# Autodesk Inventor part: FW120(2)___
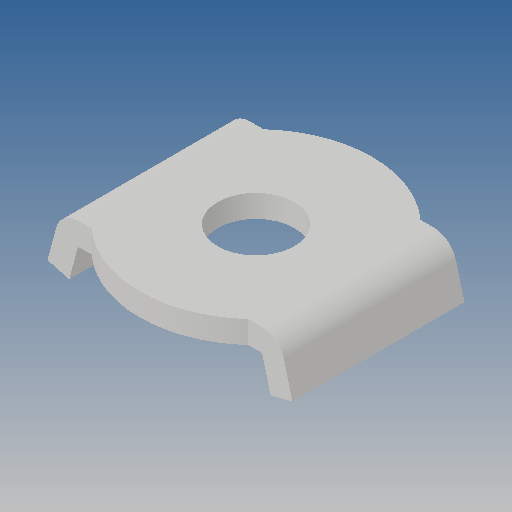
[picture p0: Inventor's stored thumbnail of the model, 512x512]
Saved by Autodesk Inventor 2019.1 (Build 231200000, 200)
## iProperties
Created: 2012-09
Part Number: FW120(2)___
Material: Ogólny
Document SubType Name: Modeling
Designer: CADENGINEERING4
Density: 1 g/cm^3
Appearance: Domyślna
Author: CADENGINEERING4
Revision Number: ÈÎºÎ
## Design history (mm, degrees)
feature "NONE"
node "Bryła1"
